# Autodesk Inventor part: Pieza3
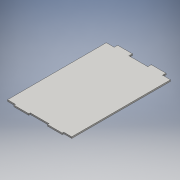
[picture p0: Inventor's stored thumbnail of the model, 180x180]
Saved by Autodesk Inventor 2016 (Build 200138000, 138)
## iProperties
Created: 2016-06
Part Number: Pieza3
Material: Genérico
Document SubType Name: Modeling
Designer: adm
Density: 1 g/cm^3
Appearance: Valor por defecto
Author: adm
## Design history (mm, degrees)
sketch "Boceto1"
  geometry: L1 (-65, -100)-(-65, 100); L2 (65, 100)-(65, -100); L3 (65, -100)-(-65, 100); L4 (-65, -100)-(65, 100); L5 (-19, -100)-(-19, -103); L6 (-19, -103)-(-49, -103); L7 (-49, -103)-(-49, -100); L8 (19, -100)-(19, -103); L9 (19, -103)-(49, -103); L10 (49, -103)-(49, -100); L11 (-19, 100)-(-19, 107); L12 (-19, 107)-(-49, 107); L13 (-49, 107)-(-49, 100); L14 (19, 107)-(49, 107); L15 (49, 107)-(49, 100); L16 (19, 100)-(19, 107); L17 (49, 100)-(65, 100); L18 (65, -100)-(49, -100); L19 (19, -100)-(-19, -100); L20 (-49, -100)-(-65, -100); L21 (-65, 100)-(-49, 100); L22 (-19, 100)-(19, 100); 1 further point
  constraints: 44 end point, 12 parallel, 5 horizontal, 5 horizontal alignment, 3 perpendicular, 2 midpoint, 2 vertical alignment
  dimensions: "d0" = 200 distance of L2.start L2.end; "d3" = 30 distance of L5.end L6.end; "d5" = 30 distance between parallel lines of L11 L13; "d6" = 16 distance between parallel lines of L13 L1; "d11" = 200 distance of L1.start L1.end; "d12" = 3 distance of L5.start L5.end; "d13" = 3 distance of L8.start L8.end; "d14" = 3 distance of L9.end L10.end; "d15" = 3 distance of L6.end L7.end; "d17" = 30 distance of L14.start L14.end; "d18" = 7 distance of L14.end L15.end; "d19" = 7 distance of L16.start L14.start; "d20" = 7 distance of L11.start L11.end; "d21" = 7 distance of L12.end L13.end; "d22" = 30 distance of L8.end L9.end; "d24" = 16 distance of L15.end L2.start
extrude "Extrusión1" new body sketch "Boceto1" distance "d8" = 3; taper "d9" = 0 deg
node "Sólido1"
